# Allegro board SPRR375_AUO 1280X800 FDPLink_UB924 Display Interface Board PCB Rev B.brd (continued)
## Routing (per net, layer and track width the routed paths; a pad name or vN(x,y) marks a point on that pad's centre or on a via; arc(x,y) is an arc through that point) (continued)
TLC5910_OUT6: length 26.4
  TOP w0.127: v3(138.68,95.63) 138.68,90.04 132.21,83.57 129.41,83.57 127.93,82.08 U12.14 ; RJ3.3 v3(143.26,95.63)
  BOTTOM w0.127: v3(138.68,95.63) v3(143.26,95.63)
TOUCH_IRQ: length 75.4
  TOP w0.127: RJ18.2 v3(169.16,88.14) ; U7.2 109.22,90.17 v3(108.84,89.79)
  BOTTOM w0.127: v3(108.84,89.79) 109.73,88.9 123.06,88.9 125.09,86.87 159.26,86.87 161.04,88.65 168.66,88.65 v3(169.16,88.14) 167.15,86.13 J3.2
TOUCH_RSTN: length 16.7
  TOP w0.127: v3(174.62,74.99) R37.1 R38.1 ; RJ19.2 v3(175.64,88.14)
  BOTTOM w0.127: v3(174.62,74.99) 174.62,87.12 v3(175.64,88.14)
TPA+: length 17
  TOP w0.127: P2.4 7.33,134.99 arc(7.54,136.03) 8.13,136.91 arc(9.25,137.66) 10.58,137.92 10.58,137.92 arc(11.56,137.73) 12.39,137.17 arc(12.9,136.41) 13.08,135.5 13.08,134.17 arc(13.28,133.18) 13.84,132.33 arc(14.52,131.88) 15.31,131.72 FL1.1
TPA-: length 17.1
  TOP w0.127: FL1.4 15.31,130.91 arc(14.52,130.75) 13.84,130.3 arc(13.37,129.6) 13.21,128.77 13.21,127.82 arc(13.01,126.83) 12.45,125.98 12.34,125.88 arc(11.75,125.49) 11.06,125.35 arc(8.94,125.77) 7.14,126.97 6.52,127.59 arc(5.64,128.91) P2.2
TPANT1: length 2.7
  TOP w0.127: R43.1 TP30.1
TPANT2: length 2.7
  TOP w0.127: R42.1 TP31.1
VEXT_DISPLAY: length 15.9
  BOTTOM w0.305: v1(17.65,157.86) 12.57,162.94 R44.2
VPOC_DISPLAY: length 87.3
  TOP w1.016: P2.3 5.35,132.45 4.27,131.78 4.27,131.78 C54.1
  L3_PWR w0.889: P2.3 6.12,133.24
  BOTTOM w0.305: R47.1 64.14,108.58 19.3,108.58 16,111.89 16,137.54 13.21,140.34 9.09,140.34
  vias: v1(6.22,139.95) v1(7.37,139.95) v1(8.38,142.11) v1(8.38,140.72)
N47950634: length 5.7
  TOP w0.127: U13.21 148.31,76.05 147.7,75.44 RJ21.2
N47950640: length 11.7
  TOP w0.127: RJ7.2 151,95.89 151,94.36 151.38,93.98 151.38,92.96 149.61,91.19 U13.2
N47950646: length 10.9
  TOP w0.127: RJ6.2 149.22,96.01 149.22,87.5 148.96,87.24 U13.3
N47950787: length 36.2
  TOP w0.127: R26.2 RJ18.1 TP17.1 169.16,92.08 170.31,90.93 U9.2 ; RJ3.2 v3(143.26,96.65)
  BOTTOM w0.127: TP17.1 156.08,92.08 152.53,95.63 146.43,95.63 145.41,96.65 v3(143.26,96.65)
N47950851: length 56.6
  TOP w0.127: U3.2 105.54,104.39 104.27,105.66 TP6.1 RJ1.3 103,102.74 102.74,103 R11.2 ; RJ5.2 v3(147,97.6)
  BOTTOM w0.127: TP6.1 105.66,105.66 106.93,104.39 118.49,104.39 125.29,97.6 v3(147,97.6)
N47950958: length 1.4
  TOP w0.127: U3.4 104.29,100.86 104.14,100.71 RJ1.1
N47950978: length 1.4
  TOP w0.127: U10.4 175.71,87.27 175.56,87.12 RJ19.1
N47951040: length 39
  TOP w0.127: U10.2 176.78,91.06 175.77,92.08 TP16.1 RJ19.3 R27.2 ; RJ4.2 v3(146.94,96.65)
  BOTTOM w0.127: v3(146.94,96.65) 147.32,96.27 152.78,96.27 155.45,93.6 168.4,93.6 169.93,92.08 TP16.1
N47952362: length 29
  TOP w0.127: 114.55,103.89 114.55,104.65 113.54,105.66 TP5.1 RJ2.3 112.01,102.74 111.76,103 R12.2 ; 114.55,103.89 119,103.89 122.17,100.71 122.17,91.82 123.06,90.93 RJ13.2 ; 114.55,103.89 U4.2
N47961891: length 2.5
  TOP w0.127: v3(77.98,81.41) 77.6,81.03 R30.2
  BOTTOM w0.127: J2.7 78,80.89 77.98,80.91 v3(77.98,81.41)
N47961914: length 3.7
  TOP w0.127: R31.1 78.87,81.03 78.61,81.28 v3(78.61,82.04)
  BOTTOM w0.127: J2.6 78.5,81.04 78.61,81.15 v3(78.61,82.04)
N47962004: length 6.3
  TOP w0.127: RJ20.2 v3(81.66,84.33)
  BOTTOM w0.127: J2.5 79,81.66 v3(81.66,84.33)
N47962200: length 6.3
  TOP w0.127: J3.1 169.32,73.03 169.44,73.15 R37.2
N47962259: length 9.5
  TOP w0.127: J3.5 163.4,74.5 165.99,77.09 R29.2
N47962261: length 3.4
  TOP w0.127: J3.4 164.65,78.94 164.72,79.01 R28.2
N47962324: length 11.3
  TOP w0.127: U6.2 104.14,89.53 104.52,89.15 105.03,89.15 RJ9.3 107.82,91.95 107.82,93.73 108.2,94.11 109.35,94.11 109.87,93.58 U7.4
N47962345: length 2
  TOP w0.127: RJ9.1 105.66,92.84 105.51,92.68 U6.4
N47969957: length 1.4
  TOP w0.127: U4.4 113.48,100.86 113.33,100.71 RJ2.1
N47970052: length 1.4
  TOP w0.127: U9.4 169.24,87.27 169.08,87.12 RJ18.3
N47970092: length 4.4
  TOP w0.127: U12.1 131.83,87.89 132.97,89.03 132.97,89.28 133.99,90.3
N47983015: length 6
  TOP w0.127: R6.1 R8.2 68.96,106.05 69.88,105.13 U5.48
N47983017: length 5.8
  TOP w0.127: R16.2 R15.1 67.18,96.52 69.51,98.85 U5.12
N47983700: length 21.3
  TOP w0.127: U5.30 77.97,101.35 78.23,101.09 79.25,101.09 79.63,100.71 83.19,100.71 84.2,101.73 84.2,104.78 ; 84.2,104.78 84.2,105.41 83.31,106.3 79.5,106.3 78.74,105.54 78.74,104.65 77.94,103.85 U5.35 ; 84.2,104.78 R9.2
N47983709: length 16.2
  TOP w0.127: U5.9 69.11,100.35 v3(69.09,100.33) R14.2 ; v3(78.48,102.32) 78.04,102.32 78.01,102.35 U5.32
  BOTTOM w0.127: v3(69.09,100.33) 71.11,102.35 78.01,102.35 78.04,102.32 v3(78.48,102.32)
N47985043: length 10
  TOP w0.127: U5.26 77.82,99.35 78.49,98.68 84.07,98.68 85.6,97.16 RJ8.2
N47986219: length 3
  TOP w0.305: U5.42 73.91,106.98 73.53,107.35 C7.2
N47992682: length 3.4
  TOP w0.127: U11.7 116.2,77.34
N48000983: length 9.6
  TOP w0.305: C31.1 R18.2 v3(41.91,92.58)
  BOTTOM w0.305: v3(42.42,86.23) 41.91,86.74 v3(41.91,92.58)
N48001081: length 6.1
  TOP w0.305: U8.4 37.34,91.99 37.47,92.11 R17.2 38.39,92.71 38.52,92.58 R18.1 C31.2
N48004915: length 2.1
  TOP w0.305: U1.1 22.15,108.38 21.78,108.01 21.78,108.01 C12.1
N48004949: length 2.2
  TOP w0.305: R5.2 14.02,106.77 13.72,106.46 C17.1
N48005041:
  vias: v1(18.29,144.27) v1(18.29,143.13) v1(18.29,142.11) v1(19.43,144.27) v1(19.43,143.13) v1(19.43,142.11) v1(24.64,112.9) v1(24.64,110.87) v1(26.04,110.87) v1(27.56,110.87) v1(28.96,110.87) v1(30.23,110.87)
N48005170: length 5
  TOP w0.203: C1.2 22.1,115.57 22.99,114.68 22.99,112.1 22.43,111.54 U1.4
N48005174: length 2.9
  TOP w0.305: U1.7 17.27,111.54 17.23,111.51 C3.2 R4.1
N48005180: length 6.7
  TOP w0.305: R13.1 R10.2 48.01,103.63 47.62,103.25 C19.2 46.35,103.25 46.23,103.12 U2.8
N48005190: length 2.7
  TOP w0.305: U2.7 45.33,102.62 46.23,101.73 47.12,101.73
N48005198: length 1.8
  TOP w0.203: R3.1 21.97,113.5 22.15,113.32 U1.5
N48005202: length 3.2
  TOP w0.203: U1.6 18.24,113.37 18.29,113.42 R2.1 17.69,114.05 17.56,114.17 R1.2
N48008865: length 9.6
  TOP w0.127: U5.28 78.35,100.35 v3(78.74,99.96)
  BOTTOM w0.127: v3(78.74,99.96) 81.04,99.96 81.79,100.71 84.2,100.71 TP8.1
N48008866: length 9.1
  TOP w0.127: U5.27 78.08,99.85 v3(78.68,99.25)
  BOTTOM w0.127: v3(78.68,99.25) 80.96,99.25 81.41,98.81 84.77,98.81 85.03,99.06 TP10.1
N48038498: length 2.6
  TOP w0.127: C45.1 12.32,75.44 12.29,75.41 U14.13
N48038546: length 6.1
  TOP w0.127: 16.76,63.37 15.49,63.37 15.49,64.26 13.59,66.17 U14.4
N48038552: length 6.3
  TOP w0.127: RJ22.2 16.89,64.14 16.38,64.14 14.24,66.28 U14.5
N48038556: length 2.8
  TOP w0.127: R33.2 14.22,75.82 14.24,75.8 U14.10
N48038560: length 7.8
  TOP w0.127: U14.6 14.89,66.26 15.62,65.53 18.29,65.53 18.67,65.15 18.67,63.63 RJ23.2
N48038564: length 3
  TOP w0.127: U14.9 14.89,75.09 15.49,75.69 R34.2
N48038573: length 8.4
  TOP w0.127: U14.7 15.54,66.36 15.98,65.91 19.18,65.91 19.94,65.15 19.94,63.63 RJ24.2
N48038577: length 3.3
  TOP w0.127: U14.8 15.54,74.61 16.76,75.84 R35.2
N48057914: length 62.1
  TOP w0.13: C8.1 71.58,119.43 arc(71.35,119.58) 71.09,119.63 71.08,119.63 70.42,119.63 arc(69.42,119.83) 68.58,120.4 arc(67.64,121.8) 67.31,123.46 67.31,125.99 arc(66.91,127.98) 65.79,129.67 65.64,129.81 65.5,129.95 arc(64.13,130.87) 62.51,131.19 18.4,131.19 arc(18.04,131.12) FL1.3
N48057923: length 62.1
  TOP w0.13: C9.1 71.51,120.02 arc(71.36,119.92) 71.19,119.89 71.19,119.89 70.42,119.89 arc(69.52,120.07) 68.76,120.58 arc(67.88,121.9) 67.57,123.46 67.57,125.99 arc(67.15,128.08) 65.97,129.85 65.68,130.13 arc(64.23,131.11) 62.51,131.45 18.4,131.45 arc(18.04,131.52) FL1.2
N48071870: length 11.9
  TOP w0.305: 15.62,151.89 17.14,151.89 19.05,149.99 19.05,149.5 19.52,149.03 U16.6 ; 15.62,151.89 15.62,151.26 15.11,150.75 15.11,149.97 15.4,149.68 U16.2 ; 15.62,151.89 Q3.4
N48071884: length 5.7
  TOP w0.305: C57.1 18.03,150.03 17.74,150.33 U16.1 16.32,150.33
N48071888: length 5.5
  TOP w0.305: C57.2 21.46,146.18 22.48,147.19 22.48,149.21 22.01,149.68 U16.7
N48071920: length 17.4
  TOP w0.508: 15.37,159.13 16.13,159.13 ; 16.13,159.13 16.13,160.02 ; 16.13,159.13 16.13,158.24 ; J1.1 9.21,153.03 ; J1.1 7.62,151.45 ; J1.1 6.03,153.03 ; J1.1 7.62,154.62 ; 16.64,155.7 Q3.2 14.6,155.7 ; Q3.1 16.64,156.97 ; Q3.1 15.62,157.65 ; Q3.1 14.6,156.97 ; 16.57,147.88 U16.4 15.36,148.38 ; 16.64,154.43 Q3.3 14.6,154.43
  vias: v2(11.81,151.38) v2(11.81,150.37) v2(11.81,149.35) v2(11.81,148.34) v2(11.81,147.32) v2(12.95,151.51) v2(12.95,146.94) v2(14.35,151.51) v2(14.35,146.94)
N48071992: length 2.1
  TOP w0.127: DS1.2 v1(2.03,162.94)
  BOTTOM w0.127: v1(2.03,162.94) R44.1
N48074547: length 9.7
  TOP w0.13: v1(75.11,112.96) arc(74.88,112.6) 74.8,112.19 74.8,105.41 arc(74.83,105.26) U5.40
  BOTTOM w0.13: v1(75.11,112.96) 75.07,113 arc(74.96,113.17) 74.92,113.37 U17.2
N48074849: length 9.7
  TOP w0.13: v1(74.22,112.96) arc(74.46,112.6) 74.54,112.19 74.54,105.44 arc(74.51,105.27) U5.41
  BOTTOM w0.13: U17.3 74.42,113.43 arc(74.37,113.18) 74.22,112.96 v1(74.22,112.96)
N48077474: length 6.4
  BOTTOM w0.127: Q1.6 67.73,113.88 68.07,113.54 R46.1 69.6,114.55 70.1,114.55 71.26,115.71 U17.7
N48078230: length 3.7
  BOTTOM w0.127: Q1.2 R48.2 R47.2 C59.2
N48128501: length 3.7
  BOTTOM w0.127: R45.2 70.88,114.69 U17.6
N480053081: length 1.7
  TOP w0.305: 15.62,112.78 15.57,112.73 13.97,112.73 C2.1
N4797957014: length 11.8
  TOP w0.127: U5.44 72.91,106.03 72.66,106.28 72.66,107.17 72.14,107.7 72.14,113.54 TP3.1
N4797957015: length 13.6
  TOP w0.127: U5.45 72.41,106.79 71.82,107.38 71.82,113.22 70.23,114.81 68.45,114.81 TP4.1

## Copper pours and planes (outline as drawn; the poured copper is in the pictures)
GND on TOP: 40.01,110.11 51.56,110.11 51.56,98.04 39.24,98.04 39.24,107.31 38.99,107.57 38.99,109.09
GND on TOP: 33.02,99.44 21.46,99.44 20.57,100.33 20.57,105.79 22.35,107.57 32.38,107.57 33.85,106.11 33.85,100.27
GND on TOP: 4.57,144.78 4.57,139.7 4.32,139.45 1.65,139.45 1.02,140.08 1.02,144.53 1.65,145.16 4.19,145.16
GND on TOP: 61.21,124.21 62.74,122.68 62.74,112.78 66.29,109.22 71.25,109.22 71.63,109.6 80.39,109.6 81.15,110.36 81.15,132.72 73.91,139.95 9.14,139.95 8.13,138.94 1.52,138.94 1.02,138.43 1.02,127.51 6.22,122.3 12.57,122.3 14.48,124.21
GND on TOP: 37.97,88.9 37.85,89.03 36.83,89.03 36.83,89.79 37.97,89.79 37.97,91.06 39.5,91.06 39.5,88.77 41.91,88.77 42.29,89.15 49.15,89.15 49.66,88.65 49.66,86.87 49.28,86.49 48.01,86.49 47.5,87 38.48,87 37.97,87.5
GND on TOP: 21.46,109.22 21.46,113.03 21.21,113.28 21.21,114.3 21.08,114.43 21.08,116.2 20.7,116.59 19.56,116.59 19.18,116.2 19.18,114.81 18.92,114.55 18.92,109.22
GND on TOP: 4.57,56.01 7.11,53.47 19.3,53.47 24.38,58.55 24.38,76.83 19.56,81.66 8.64,81.66 4.57,77.6
GND on BOTTOM: 27.69,152.02 27.69,147.19 28.19,146.69 30.86,146.69 31.5,147.32 31.5,151.51 30.48,152.53 28.19,152.53
GND on BOTTOM: 60.83,80.64 60.83,78.99 62.99,76.83 62.99,75.82 62.74,75.56 57.66,75.56 56.52,76.71 56.52,79.38 57.78,80.64
GND on BOTTOM: 81.66,80.64 81.66,78.99 79.63,76.96 79.63,75.82 79.88,75.56 84.84,75.56 85.98,76.71 85.98,79.38 84.71,80.64
GND on L2_GND: 0.64,173.1 0.89,173.35 250.19,173.35 250.44,173.1 250.44,0.89 250.19,0.64 176.91,0.64 176.91,3.43 120.27,3.43 120.27,0.64 0.89,0.64 0.64,0.89 ; 1 cut-out
VCC_LED on TOP: 54.36,80.39 54.36,85.22 55.18,86.04 69.66,86.04 70.74,84.96 70.74,80.14 69.22,78.61 56.13,78.61
VDD33_AB on TOP: 75.69,105.03 75.69,107.57 76.71,108.58 80.26,108.58 80.64,108.2 80.64,106.93 79.12,106.93 77.22,105.03
VDD33_AB on BOTTOM: 78.61,100.84 80.14,100.84 81.15,101.85 81.15,106.68 79.76,108.08 77.22,108.08 76.71,107.57 76.71,105.28 77.85,104.14 77.85,101.6
VDDIO on TOP: 67.06,98.81 69.85,101.6 70.74,101.6 70.74,102.11 68.83,102.11 67.94,103 66.55,103 66.29,102.74 66.29,99.06 66.55,98.81
VDDIO on BOTTOM: 68.07,101.73 68.07,103.25 68.58,103.76 71.88,103.76 74.8,106.68 74.8,113.92 74.42,114.3 72.39,114.3 71.25,113.16 71.25,110.36 66.67,105.79 66.67,101.98 67.31,101.35 67.69,101.35
DC_5V on TOP: 42.29,101.85 42.29,102.74 41.27,102.74 41.27,103.5 42.16,103.5 42.16,106.68 41.66,107.19 39.24,107.19 38.35,106.3 35.81,106.3 34.29,104.78 34.29,100.08 33.15,98.93 24.77,98.93 24.64,99.06 22.23,99.06 21.72,98.55 21.72,92.71 24,90.42 24,79.88 26.92,76.96 37.34,76.96 39.12,78.74 39.12,81.15 37.34,82.93 28.45,82.93 27.69,83.69 27.69,87.88 28.83,89.03 36.2,89.03 36.2,94.87 38.86,97.54 38.86,100.84 38.99,100.97 41.4,100.97
EVM_3V3 on TOP: 8.64,65.28 11.18,65.28 11.81,65.91 11.81,68.33 11.68,68.45 11.3,68.45 10.67,67.82 8.76,67.82 8.13,67.18 8.13,65.79
EVM_3V3 on TOP: 49.78,107.31 49.78,104.65 48.13,104.65 47.37,103.89 46.1,103.89 45.72,103.5 44.45,103.5 44.45,105.16 45.21,105.92 45.21,107.31
EVM_3V3 on TOP: 90.93,80.01 93.22,80.01 93.73,80.52 93.73,82.04 93.09,82.68 91.06,82.68 90.42,82.04 90.42,80.52
EVM_3V3 on TOP: 79.76,79.38 81.66,79.38 82.55,80.26 82.55,81.66 82.04,82.17 80.01,82.17 79.25,81.41 79.25,79.88
EVM_3V3 on L3_PWR: 0.64,173.1 0.89,173.35 250.19,173.35 250.44,173.1 250.44,0.89 250.19,0.64 176.66,0.64 176.66,3.17 120.78,3.17 120.78,0.64 0.89,0.64 0.64,0.89 0.64,129.03 7.49,129.03 7.49,137.03 9.78,139.32 9.78,142.24 8.13,143.89 0.64,143.89 ; 1 cut-out
VEXT_DISPLAY on TOP: 17.27,158.24 18.54,158.24 19.43,159.13 25.91,159.13 29.59,155.45 29.59,142.49 28.32,141.22 24.13,141.22 23.37,141.99 23.37,149.61 22.86,150.11 19.94,150.11 17.27,152.78
VPOC_DISPLAY on TOP: 10.03,144.91 6.48,144.91 5.46,143.89 5.46,139.83 5.97,139.32 7.75,139.32 10.41,141.99 10.41,144.53
VPOC_DISPLAY on BOTTOM: 5.21,131.83 7.11,131.83 9.27,133.99 9.27,141.86 8.76,142.37 4.83,142.37 3.68,141.22 3.68,133.35
VPOC_DISPLAY on L3_PWR: 6.99,137.29 6.99,131.83 5.33,131.83 4.7,132.46 4.7,133.73 1.52,136.91 0.64,136.91 0.64,143.51 8,143.51 9.27,142.24 9.27,139.57
N48000930 on TOP: 37.59,88.65 37.59,83.95 37.08,83.44 29.21,83.44 28.19,84.45 28.19,87.63 29.15,88.58 29.78,88.58 29.84,88.65
N48000983 on TOP: 39.5,86.11 39.5,83.06 40.13,82.42 52.07,82.42 52.83,83.19 52.83,85.22 52.2,85.85 48.26,85.85 47.75,85.34 43.05,85.34 42.67,85.72 42.67,86.36 39.75,86.36
N48004919 on TOP: 18.92,109.47 18.92,110.11 16.38,110.11 15.49,109.22 15.49,92.46 16,91.95 19.3,91.95 20.19,92.84 20.19,107.31 19.56,107.95 18.29,107.95 17.65,108.58 17.65,109.47
N48005041 on TOP: 21.72,109.6 22.61,109.6 22.61,108.08 32.26,108.08 33.27,109.09 33.27,113.41 31.88,114.81 24.26,114.81 23.62,114.17 23.62,111.38 23.37,111.12 21.84,111.12 21.72,111
N48005041 on TOP: 12.19,141.73 21.59,141.73 21.59,144.91 12.19,144.91 11.81,144.53 11.81,142.11
N48005041 on BOTTOM: 17.27,144.91 17.27,116.46 24.13,109.6 30.86,109.6 32.26,111 32.26,140.59 27.3,145.54 17.91,145.54
N48071920 on TOP: 16.89,152.53 15.88,151.51 15.88,149.73 16.89,148.72 16.89,146.18 6.99,146.18 3.94,149.22 3.94,159.38 7.24,162.69 16.89,162.69
N48071920 on BOTTOM: 15.24,146.3 15.24,152.02 11.05,152.02 11.05,146.3
N48071988 on BOTTOM: 24.77,147.57 24.77,151.13 18.16,151.13 18.16,147.57 18.54,147.19 24.38,147.19

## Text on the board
BOTTOM: LOGIC 518402 REV B | PWB 518401 REV B | LAYER 4 | SOLDER
Board Geometry/Soldermask Bottom: SMS
Ref Des/Silkscreen Bottom: GND | VCC | 12V-16V | VCC_LED | LCD CONNECTOR | NOT FCC APPROVED FOR RESALE | FOR EVALUATION ONLY; | ANT1 | ANT2 | S/N | ASSY 518400 REV | BSLK
TOP: COMPONENT | LAYER 1
Board Geometry/Soldermask Top: SMC
Ref Des/Silkscreen Top: GND | 924 FPD-LINK INTERFACE DISPLAY ADAPTER | TSLK
L2_GND: LAYER 2 | GND
L3_PWR: LAYER 3 | PWR
USER_PART_NUM_TOP: TSLKC
DIMENSION: DRILL
USER_PART_NUM_BOTTOM: BSLKC
DISPLAY_BOTTOM: GND | 39 | 1 | 2 | 120 | 119 | 40 | EXPANSION | LCD | INTERFACE | MICRO-SD | SPS | +
DISPLAY_TOP: SPC
BODY_CENTER: 40 | 1 | 6
User.9: DATE | DESIGN ENGR | PROJECT ENGR | ENGR MGR | NEXT ASSEMBLY | APPROVED | CHECKED | DRAFTING | ENGR | NONE | 1 OF 1 | NOTES: UNLESS OTHERWISE SPECIFIED | 100 OHM DIFFERENTIAL +/-10%: 5.1 MIL TRACE EXTERNAL. | 1   TOTAL BOARD THICKNESS SHALL BE .062 +/- .007 INCHES. | 4.  SOLDERMASK ON BOTH SIDES OF THE BOARD SHALL BE S.M.O.B.C., LPI, COLOR BLACK, MATTE. | 3.  MINIMUM TRACE AND SPACE SHALL BE .005 OF AN INCH. | 2.  COPPER PLATED SURFACE CONDUCTORS SHALL BE THE EQUIVALENT OF 1 OZ. COPPER | 6.  FINISHED BOARD SHALL BE FREE OF BURRS ON EDGES. | 5.  PLATED THRU HOLE SIZE TOLERANCES SHALL BE +/- .003 INCH. | 8.  IMPEDANCE CONTROL TO 50 OHMS FOR 5 MIL TRACES. | 7.  SURFACE FINISH SHALL BE IMMERSION GOLD. | AFTER PLATING.  PLANE LAYERS SHALL BE 1 OZ. COPPER.  AVERAGE COPPER ON | THE WALL OF THE PLATED HOLE SHALL BE .001 INCH. | ALL MATERIAL SHALL BE NEMA GRADE FR-4 OR EQUIVALENT. (Tg>=170 DEG. C) | UNPLATED THRU HOLE SIZE TOLERANCES SHALL BE +/- .002 INCH.
User.10: DATE | DESIGN ENGR | PROJECT ENGR | ENGR MGR | NEXT ASSEMBLY | APPROVED | CHECKED | DRAFTING | ENGR | 1 OF 1
User.13: 1. All board outlines shall be .020 in width. | 2. All other lines shall be .012 in width. | 3. Note and misc. text shall be text block 10. | 4. View and description text shall be text block 16. | 5. Make sure that there is not any double dimensioning, | 6. Check all notes to make sure that they apply and are correct. | 7. Make sure that layer stack-up is correct. | label (REF) dim when needed.
User.14: FIGURE | SIZE | 8.0 | 10.0 | 12.0 | 13.0 | 20.0 | 32.0 | 35.0 | 39.0 | 40.0 | 47.0 | 55.0 | 63.0 | 67.0 | 125.0 | PLATED | DRILL CHART | ALL UNITS ARE IN MILS | QTY | 9 | 78 | 395 | 33 | 5 | 2 | 15 | 6 | 8 | 4 | 16 | 1 | TOL | NOTE
